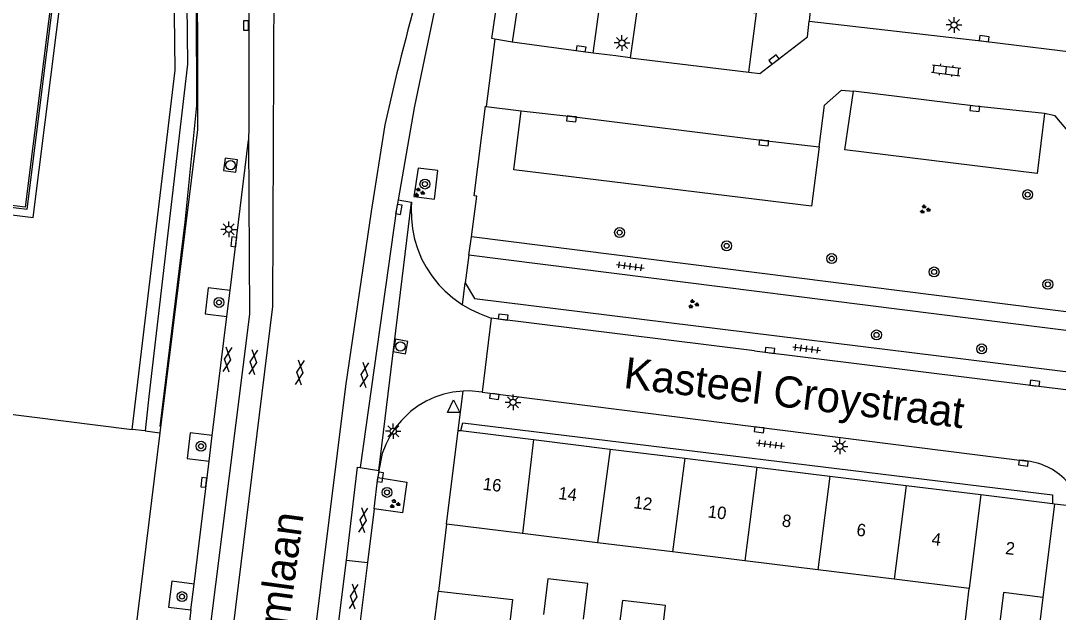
# Model space of a CAD drawing. Extents: x 131000 to 133014, y 396499 to 399001.
# Drawn here: x 131618.1 to 131701.6, y 396881.2 to 396928.8 of the extents above; entities that cross this region are included whole.
import ezdxf

# ---------------------------------------------------------------- set-up
doc = ezdxf.new("R2010")
doc.units = 0
for name, color, linetype in [('gg-afsc-hekwerk', 7, 'Continuous'), ('gg-afsc-muur', 7, 'Continuous'), ('gg-anno-huisnummerreeks BGT', 7, 'Continuous'), ('gg-anno-openbare ruimte label', 7, 'Continuous'), ('gg-bbg-bijgebouw', 7, 'Continuous'), ('gg-bbg-gedigitaliseerde bebouwing', 7, 'Continuous'), ('gg-bbg-gedigitaliseerde bijgebouw', 7, 'Continuous'), ('gg-bbg-hoofdgebouw', 7, 'Continuous'), ('gg-bbg-luifel en loopbrug', 7, 'Continuous'), ('gg-bbg-tussenscheiding', 7, 'Continuous'), ('gg-knt-verharding', 7, 'Continuous'), ('gg-knt-verharding nz', 7, 'Continuous'), ('gt-grn-groengrens', 7, 'Continuous'), ('gt-grn-weggrens', 7, 'Continuous'), ('gt-symb-boom', 7, 'Continuous'), ('gt-symb-gesloten verharding', 7, 'Continuous'), ('gt-symb-groenvak', 7, 'Continuous'), ('gt-symb-klinker verharding', 7, 'Continuous'), ('gt-symb-kolk', 7, 'Continuous'), ('gt-symb-lichtmast', 7, 'Continuous'), ('gt-symb-rioolschacht', 7, 'Continuous'), ('gt-symb-tegel verharding', 7, 'Continuous'), ('gt-symb-waterafsluiter', 7, 'Continuous')]:
    doc.layers.add(name, color=color, linetype=linetype)

# ---------------------------------------------------------------- blocks, each defined once
blk = doc.blocks.new('gt0-KOLK')
at = {"layer": 'gt-symb-kolk'}
blk.add_lwpolyline([(0, 0), (0.375, 0), (0.375, 0.4), (-0.375, 0.4), (-0.375, 0), (0, 0)], dxfattribs=at)
blk = doc.blocks.new('gt0-TEG1')
at = {"layer": 'gt-symb-tegel verharding'}
for p, q in [((-1.125, 0), (1.125, 0)), ((-0.9, -0.25), (-0.9, 0.25)), ((-0.45, -0.25), (-0.45, 0.25)), ((0, -0.25), (0, 0.25)), ((0.45, -0.25), (0.45, 0.25)), ((0.9, -0.25), (0.9, 0.25))]:
    blk.add_line(p, q, dxfattribs=at)
blk = doc.blocks.new('gt0-GRVAK')
at = {"layer": 'gt-symb-groenvak'}
for p, q in [((-0.11, 0.189), (-0.228, 0.24)), ((-0.182, 0.153), (0.088, 0.153)), ((-0.091, 0.211), (-0.156, 0.322)), ((-0.047, 0.214), (-0.047, 0.393)), ((-0.004, 0.211), (0.061, 0.322)), ((0.015, 0.189), (0.133, 0.24)), ((0.262, -0.052), (0.197, 0.059)), ((0.305, -0.049), (0.305, 0.13)), ((0.349, -0.052), (0.414, 0.059)), ((-0.245, -0.228), (-0.363, -0.177)), ((-0.318, -0.264), (-0.047, -0.264)), ((-0.226, -0.206), (-0.291, -0.095)), ((-0.183, -0.203), (-0.183, -0.024)), ((-0.139, -0.206), (-0.074, -0.095)), ((-0.12, -0.228), (-0.002, -0.177)), ((0.243, -0.074), (0.125, -0.023)), ((0.17, -0.11), (0.441, -0.11)), ((0.368, -0.074), (0.486, -0.023))]:
    blk.add_line(p, q, dxfattribs=at)
blk = doc.blocks.new('gt0-LMAST')
at = {"layer": 'gt-symb-lichtmast'}
for p, q in [((-0.182, 0.173), (-0.447, 0.438)), ((-0.005, 0.246), (-0.005, 0.621)), ((0.172, 0.173), (0.437, 0.438)), ((-0.255, -0.004), (-0.63, -0.004)), ((-0.182, -0.181), (-0.447, -0.446)), ((-0.005, -0.254), (-0.005, -0.629)), ((0.437, -0.446), (0.172, -0.181)), ((0.245, -0.004), (0.62, -0.004))]:
    blk.add_line(p, q, dxfattribs=at)
blk.add_circle((-0.005, -0.004), 0.25, dxfattribs=at)
blk = doc.blocks.new('gt0-GESVH1')
at = {"layer": 'gt-symb-gesloten verharding'}
for p, q in [((-0.992, -0.261), (0.008, 0.239)), ((0.008, -0.261), (-0.992, 0.239)), ((0.008, 0.239), (1.008, -0.261)), ((1.008, 0.239), (0.008, -0.261))]:
    blk.add_line(p, q, dxfattribs=at)
blk = doc.blocks.new('gt0-BOOM')
at = {"layer": 'gt-symb-boom'}
for radius in [0.4, 0.2]:
    blk.add_circle((0, 0), radius, dxfattribs=at)
blk = doc.blocks.new('gt0-KL1')
at = {"layer": 'gt-symb-klinker verharding'}
for p, q in [((-1.15, 0.3), (1.15, 0.3)), ((-1, -0.3), (-1, 0.3)), ((-0.5, 0.3), (-0.5, 0.45)), ((0, -0.3), (0, 0.3)), ((0.5, 0.3), (0.5, 0.45)), ((1, -0.3), (1, 0.3)), ((-1.15, -0.3), (1.15, -0.3)), ((-0.5, -0.45), (-0.5, -0.3)), ((0.5, -0.45), (0.5, -0.3))]:
    blk.add_line(p, q, dxfattribs=at)
blk = doc.blocks.new('gt0-RS')
at = {"layer": 'gt-symb-rioolschacht'}
blk.add_lwpolyline([(-0.5, -0.5), (0.5, -0.5), (0.5, 0.5), (-0.5, 0.5)], close=True, dxfattribs=at)
blk.add_circle((0, 0), 0.375, dxfattribs=at)
blk = doc.blocks.new('gt0-WAFSL')
at = {"layer": 'gt-symb-waterafsluiter'}
for p, q in [((-0.5, -0.333), (0, 0.667)), ((0, 0.667), (0.5, -0.333)), ((0.5, -0.333), (-0.5, -0.333))]:
    blk.add_line(p, q, dxfattribs=at)

msp = doc.modelspace()

# ---------------------------------------------------------------- linework, layer by layer
at = {"layer": 'gg-afsc-hekwerk'}
for points in [[(131629.348, 396896.143), (131631.366, 396912.594), (131632.311, 396921.975), (131632.216, 396945.592)], [(131603.59, 396936.588), (131600.935, 396915.763), (131618.639, 396913.615), (131621.794, 396938.711), (131604.126, 396940.953), (131603.672, 396937.231)]]:
    msp.add_lwpolyline(points, dxfattribs=at)
at = {"layer": 'gg-afsc-muur'}
for p, q in [((131652.39, 396888.28), (131651.73, 396882.9)), ((131700.36, 396882.38), (131699.58, 396876.07))]:
    msp.add_line(p, q, dxfattribs=at)
at = {"layer": 'gg-bbg-bijgebouw'}
msp.add_line((131651.34, 396879.73), (131651.73, 396882.9), dxfattribs=at)
at = {"layer": 'gg-bbg-gedigitaliseerde bebouwing'}
for p, q in [((131658.498, 396887.529), (131652.39, 396888.28)), ((131664.542, 396886.785), (131658.498, 396887.529)), ((131670.578, 396886.043), (131664.542, 396886.785)), ((131676.378, 396885.329), (131670.578, 396886.043)), ((131682.247, 396884.607), (131676.378, 396885.329)), ((131688.396, 396883.851), (131682.247, 396884.607)), ((131694.444, 396883.106), (131688.396, 396883.851)), ((131694.049, 396879.873), (131694.444, 396883.106))]:
    msp.add_line(p, q, dxfattribs=at)
at = {"layer": 'gg-bbg-gedigitaliseerde bijgebouw'}
msp.add_lwpolyline([(131651.73, 396882.9), (131657.703, 396882.21), (131657.332, 396878.993)], dxfattribs=at)
at = {"layer": 'gg-bbg-hoofdgebouw'}
for p, q in [((131652.39, 396888.28), (131653.33, 396895.83)), ((131653.33, 396895.83), (131653.53, 396895.805)), ((131653.53, 396895.805), (131659.381, 396895.085)), ((131659.381, 396895.085), (131665.545, 396894.327)), ((131665.545, 396894.327), (131671.55, 396893.588)), ((131671.55, 396893.588), (131677.351, 396892.875)), ((131677.351, 396892.875), (131683.214, 396892.153)), ((131683.214, 396892.153), (131689.358, 396891.397)), ((131689.358, 396891.397), (131695.368, 396890.658)), ((131695.368, 396890.658), (131701.14, 396889.948)), ((131701.29, 396889.93), (131700.36, 396882.38)), ((131701.14, 396889.948), (131701.29, 396889.93))]:
    msp.add_line(p, q, dxfattribs=at)
msp.add_lwpolyline([(131700.36, 396882.38), (131697.18, 396882.77), (131696.78, 396879.54), (131694.049, 396879.873)], dxfattribs=at)
at = {"layer": 'gg-bbg-luifel en loopbrug'}
for points in [[(131663.398, 396880.632), (131663.75, 396883.497), (131660.549, 396883.89), (131660.195, 396881.002)], [(131669.78, 396879.857), (131670.009, 396881.724), (131666.531, 396882.151), (131666.302, 396880.286)]]:
    msp.add_lwpolyline(points, dxfattribs=at)
at = {"layer": 'gg-bbg-tussenscheiding'}
for p, q in [((131659.381, 396895.085), (131658.498, 396887.529)), ((131665.545, 396894.327), (131664.542, 396886.785)), ((131671.55, 396893.588), (131670.578, 396886.043)), ((131677.351, 396892.875), (131676.378, 396885.329)), ((131683.214, 396892.153), (131682.247, 396884.607)), ((131689.358, 396891.397), (131688.396, 396883.851)), ((131695.368, 396890.658), (131694.444, 396883.106))]:
    msp.add_line(p, q, dxfattribs=at)
at = {"layer": 'gg-knt-verharding'}
for p, q in [((131682.08, 396933.83), (131681.549, 396928.756)), ((131658.355, 396931.783), (131657.672, 396927.065)), ((131664.186, 396926.186), (131664.831, 396930.912)), ((131667.827, 396930.533), (131667.154, 396925.811)), ((131656.265, 396927.316), (131655.567, 396921.896)), ((131657.672, 396927.065), (131656.265, 396927.316)), ((131666.004, 396925.956), (131664.186, 396926.186)), ((131667.154, 396925.811), (131666.004, 396925.956)), ((131655.567, 396921.896), (131658.397, 396921.534)), ((131634.972, 396907.08), (131636.466, 396919.19)), ((131710.322, 396904.35), (131654.385, 396911.394)), ((131654.188, 396909.921), (131653.89, 396907.69)), ((131710.154, 396902.854), (131654.188, 396909.921)), ((131634.715, 396904.984), (131634.972, 396907.08)), ((131633.543, 396895.416), (131634.715, 396904.984)), ((131655.988, 396904.868), (131655.251, 396898.892)), ((131677.168, 396902.216), (131655.988, 396904.868)), ((131677.168, 396902.216), (131703.58, 396898.94)), ((131655.251, 396898.892), (131670.505, 396896.983)), ((131670.505, 396896.983), (131699.12, 396893.36)), ((131629.325, 396895.632), (131626.651, 396874.007)), ((131633.288, 396893.34), (131633.543, 396895.416)), ((131632.078, 396883.464), (131633.288, 396893.34)), ((131645.44, 396892.848), (131646.949, 396892.593)), ((131646.562, 396889.513), (131646.871, 396892.029)), ((131646.949, 396892.593), (131646.871, 396892.029)), ((131701.13, 396890.63), (131701.14, 396889.948)), ((131646.562, 396889.513), (131646.028, 396885.184)), ((131646.028, 396885.184), (131645.422, 396880.263)), ((131631.823, 396881.384), (131632.078, 396883.464)), ((131631.823, 396881.384), (131630.563, 396871.097))]:
    msp.add_line(p, q, dxfattribs=at)
for points in [[(131632.291, 396954.634), (131632.342, 396920.036), (131629.325, 396895.632)], [(131657.121, 396947.074), (131655.426, 396941.468), (131651.433, 396929.642), (131649.774, 396921.772), (131648.485, 396914.385)], [(131636.468, 396944.784), (131636.495, 396920.237), (131636.466, 396919.19)], [(131593.99, 396937.342), (131601.455, 396936.385), (131601.264, 396934.895), (131602.74, 396934.696), (131600.326, 396915.3), (131619.127, 396912.948), (131622.425, 396939.187), (131603.627, 396941.586), (131603.324, 396939.29), (131601.842, 396939.476), (131601.662, 396937.997), (131594.197, 396938.955)], [(131621.602, 396938.58), (131618.489, 396913.785), (131601.128, 396915.94), (131604.253, 396940.755), (131621.602, 396938.58)], [(131656.265, 396927.316), (131656.032, 396927.358), (131656.743, 396932.313)], [(131676.694, 396924.643), (131677.326, 396929.396), (131667.827, 396930.533)], [(131676.694, 396924.643), (131677.583, 396924.544), (131681.416, 396927.482), (131681.549, 396928.756)], [(131682.361, 396918.652), (131682.787, 396922.008), (131684.168, 396923.197), (131685.119, 396923.112)], [(131700.5, 396921.32), (131699.895, 396916.49), (131684.424, 396918.39), (131685.119, 396923.112)], [(131654.385, 396911.394), (131654.822, 396914.666), (131654.615, 396914.705), (131655.513, 396921.903), (131655.567, 396921.896)], [(131682.361, 396918.652), (131681.756, 396913.876), (131657.789, 396916.796), (131658.397, 396921.534)], [(131704.978, 396915.743), (131705.092, 396916.677), (131701.343, 396921.141), (131700.5, 396921.32)], [(131649.746, 396914.634), (131651.432, 396914.434), (131651.69, 396916.747), (131650.099, 396916.924), (131649.746, 396914.634)], [(131648.485, 396914.385), (131648.356, 396913.646), (131645.44, 396892.848)], [(131634.972, 396907.08), (131633.216, 396907.295), (131632.961, 396905.199), (131634.715, 396904.984)], [(131653.89, 396907.69), (131654.63, 396906.43), (131709.795, 396899.638)], [(131653.53, 396895.805), (131653.69, 396896.44), (131701.13, 396890.63)], [(131633.543, 396895.416), (131631.77, 396895.633), (131631.512, 396893.558), (131633.288, 396893.34)], [(131646.871, 396892.029), (131649.19, 396891.661), (131648.855, 396889.186), (131646.562, 396889.513)], [(131632.078, 396883.464), (131630.288, 396883.683), (131630.033, 396881.603), (131631.823, 396881.384)]]:
    msp.add_lwpolyline(points, dxfattribs=at)
msp.add_arc((131698.404, 396888.04), 5.368, 41.81588, 82.3383, dxfattribs=at)
at = {"layer": 'gg-knt-verharding nz'}
for p, q in [((131664.186, 396926.186), (131657.672, 396927.065)), ((131667.154, 396925.811), (131676.694, 396924.643)), ((131646.949, 396892.593), (131649.575, 396914.196)), ((131643.733, 396880.479), (131644.333, 396885.393)), ((131644.333, 396885.393), (131646.028, 396885.184))]:
    msp.add_line(p, q, dxfattribs=at)
for points in [[(131614.875, 396715.283), (131622.628, 396778.427), (131628.649, 396826.47), (131638.415, 396905.786), (131638.564, 396944.76)], [(131681.549, 396928.756), (131695.61, 396927.148), (131704.378, 396926.074)], [(131700.5, 396921.32), (131694.912, 396921.925), (131685.119, 396923.112)], [(131658.397, 396921.534), (131662.463, 396921.09), (131677.937, 396919.162), (131682.361, 396918.652)], [(131647.414, 396920.421), (131646.322, 396913.453), (131644.267, 396899.385), (131629.508, 396780.775), (131621.21, 396714.486)], [(131636.466, 396919.19), (131636.53, 396905.169), (131626.678, 396826.704), (131624.286, 396806.544), (131623.827, 396806.598)], [(131644.333, 396885.393), (131645.216, 396892.874), (131645.44, 396892.848)]]:
    msp.add_lwpolyline(points, dxfattribs=at)
msp.add_arc((131887.233, 396865.764), 245.968, 161.8409, 167.16112, dxfattribs=at)
at = {"layer": 'gt-grn-groengrens'}
for p, q in [((131591.879, 396900.29), (131627.087, 396895.91)), ((131628.135, 396895.779), (131627.087, 396895.91)), ((131628.135, 396895.779), (131629.325, 396895.632))]:
    msp.add_line(p, q, dxfattribs=at)
msp.add_lwpolyline([(131627.087, 396895.91), (131630.57, 396924.812), (131630.231, 396951.712), (131630.055, 396954.142), (131631.207, 396954.228), (131631.265, 396951.781), (131631.557, 396925.296), (131628.432, 396898.546), (131628.135, 396895.779)], dxfattribs=at)
at = {"layer": 'gt-grn-weggrens'}
for p, q in [((131648.485, 396914.385), (131649.575, 396914.196)), ((131654.188, 396909.921), (131654.385, 396911.394)), ((131653.683, 396905.933), (131653.89, 396907.69)), ((131653.33, 396895.83), (131653.723, 396898.984)), ((131701.29, 396889.93), (131703.429, 396889.667))]:
    msp.add_line(p, q, dxfattribs=at)
for points in [[(131649.575, 396914.196), (131649.544, 396913.708), (131649.557, 396912.871), (131649.647, 396912.037), (131649.816, 396911.215), (131650.041, 396910.471), (131650.383, 396909.639), (131650.748, 396908.949), (131651.2, 396908.255), (131651.766, 396907.548), (131652.253, 396907.043), (131652.885, 396906.494), (131653.683, 396905.933)], [(131653.683, 396905.933), (131654.291, 396905.583), (131655.053, 396905.234), (131655.988, 396904.868)], [(131653.723, 396898.984), (131652.908, 396898.903), (131652.168, 396898.739), (131651.449, 396898.497), (131650.76, 396898.181), (131650.108, 396897.794), (131649.5, 396897.34), (131649.3, 396897.167), (131648.754, 396896.623), (131648.268, 396896.026), (131647.846, 396895.381), (131647.494, 396894.696), (131647.214, 396893.979), (131646.949, 396892.593)], [(131655.251, 396898.892), (131654.213, 396899.002), (131653.723, 396898.984)]]:
    msp.add_lwpolyline(points, dxfattribs=at)

# ---------------------------------------------------------------- block references
at = {"layer": 'gt-symb-boom'}
for p in [(131650.652, 396915.647), (131699.135, 396914.797), (131666.313, 396911.746), (131674.92, 396910.676), (131683.37, 396909.654), (131691.609, 396908.576), (131700.763, 396907.578), (131634.083, 396906.119), (131686.982, 396903.509), (131695.438, 396902.388), (131632.637, 396894.556), (131647.6, 396890.837), (131631.109, 396882.454)]:
    msp.add_blockref('gt0-BOOM', p, dxfattribs=at)
at = {"layer": 'gt-symb-gesloten verharding'}
for p, rotation in [((131634.781, 396901.54), -96.83367234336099), ((131636.859, 396901.332), -96.83367234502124), ((131640.599, 396900.501), -96.83367234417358), ((131645.793, 396900.293), -96.83367234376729), ((131645.693, 396888.606), -96.83367234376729), ((131644.934, 396882.461), -96.83367234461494)]:
    msp.add_blockref('gt0-GESVH1', p, dxfattribs=dict(at, rotation=rotation))
at = {"layer": 'gt-symb-groenvak'}
for p in [(131650.17, 396914.964), (131690.865, 396913.611), (131672.234, 396905.986), (131648.21, 396889.908)]:
    msp.add_blockref('gt0-GRVAK', p, dxfattribs=at)
at = {"layer": 'gt-symb-klinker verharding', "rotation": -7.004259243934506}
msp.add_blockref('gt0-KL1', (131692.583, 396924.807), dxfattribs=at)
at = {"layer": 'gt-symb-kolk'}
for p, rotation in [((131636.464, 396928.408), 89.54164354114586), ((131695.609, 396927.148), -7.00425924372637), ((131663.182, 396926.329), -8.049061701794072), ((131678.845, 396925.508), 36.950127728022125), ((131694.912, 396921.925), 173.33703637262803), ((131662.462, 396921.09), 173.10945167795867), ((131677.937, 396919.162), 172.9318599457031), ((131648.356, 396913.646), -99.9050792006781), ((131635.472, 396910.976), 82.93185994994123), ((131656.926, 396904.747), -7.295560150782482), ((131678.38, 396902.063), -6.947410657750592), ((131699.686, 396899.423), -7.181878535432), ((131656.257, 396898.756), 172.29934460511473), ((131677.568, 396896.072), 172.06444962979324), ((131698.819, 396893.395), 172.53402593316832), ((131633.064, 396891.62), 83.10945167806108), ((131646.874, 396892.088), -98.45426172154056)]:
    msp.add_blockref('gt0-KOLK', p, dxfattribs=dict(at, rotation=rotation))
at = {"layer": 'gt-symb-lichtmast'}
for p in [(131693.223, 396928.454), (131666.508, 396927.007), (131634.868, 396912.008), (131657.745, 396898.088), (131648.103, 396895.765), (131684.038, 396894.546)]:
    msp.add_blockref('gt0-LMAST', p, dxfattribs=at)
at = {"layer": 'gt-symb-rioolschacht'}
for p, rotation in [((131635.014, 396917.172), -97.53025334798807), ((131648.682, 396902.58), 79.04956573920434)]:
    msp.add_blockref('gt0-RS', p, dxfattribs=dict(at, rotation=rotation))
at = {"layer": 'gt-symb-tegel verharding'}
for p, rotation in [((131667.166, 396909.032), -7.125016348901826), ((131681.353, 396902.396), -7.238726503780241), ((131678.449, 396894.693), -7.23872650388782)]:
    msp.add_blockref('gt0-TEG1', p, dxfattribs=dict(at, rotation=rotation))
at = {"layer": 'gt-symb-waterafsluiter'}
msp.add_blockref('gt0-WAFSL', (131652.958, 396897.607), dxfattribs=at)

# ---------------------------------------------------------------- texts
at = {"layer": 'gg-anno-huisnummerreeks BGT'}
for s, p in [('16', (131655.27, 396891.057)), ('14', (131661.342, 396890.31)), ('12', (131667.394, 396889.566)), ('10', (131673.365, 396888.832)), ('8', (131679.324, 396888.098)), ('6', (131685.328, 396887.359)), ('4', (131691.369, 396886.616)), ('2', (131697.303, 396885.886))]:
    msp.add_text(s, height=1, rotation=353, dxfattribs=at).set_placement(p)
at = {"layer": 'gg-anno-openbare ruimte label'}
for s, rotation, p in [('Kasteel Croystraat', 353.2, (131666.565, 396899.254)), ('Conservatoriumlaan', 82.3, (131636.89, 396859.422))]:
    msp.add_text(s, height=2.5, rotation=rotation, dxfattribs=at).set_placement(p)

doc.saveas('drawing.dxf')
